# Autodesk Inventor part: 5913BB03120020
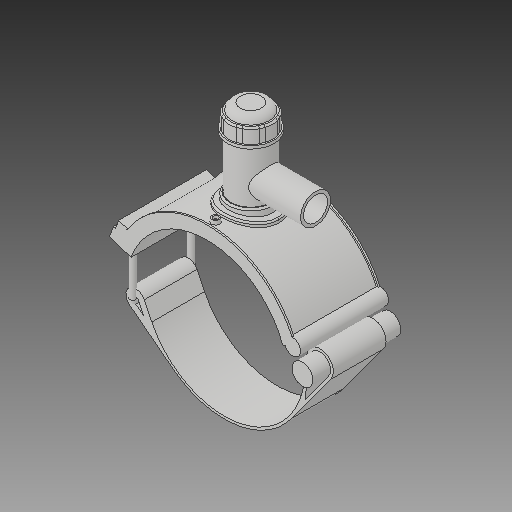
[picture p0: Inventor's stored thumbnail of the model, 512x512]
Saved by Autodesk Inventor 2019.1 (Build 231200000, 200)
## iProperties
Created: 2017-07
Part Number: 5913BB03120020
Material: Generic
Description: PLASSON HIGH VOLUME TAPPING TEE 12''IPS x 2''IPS
Document SubType Name: Modeling
Designer: KIM
Mass: 1712.7 g
Surface Area: 2671.49 cm^2
Volume: 1712.7 cm^3
Density: 1 g/cm^3
Appearance: Default
Author: KIM
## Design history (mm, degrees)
derived "5913B.ipt"
feature "Solid1::5913B.ipt"
feature "Solid2::5913B.ipt"
feature "Solid4::5913B.ipt"
feature "Solid5::5913B.ipt"
tag "TaggingFeature1"
body "Solid1"
body "Solid2"
other parameters: "d0" = 323.4, "d2" = 487.045, "d3" = 80.85, "d4" = 176.022, "d5" = 0, "d6" = 0.1, "d8" = 0, "d40" = 191.71152, "d41" = 113.19, "d43" = 0, "d45" = 0, "d47" = 289.9512, "d78" = 191.7, "d79" = 15, "d80" = 70.4088, "d82" = 5 deg, "d84" = 4, "d85" = 14, "d86" = 0, "d87" = 3, "d88" = 0, "d96" = 376.04952, "d97" = 3.52044, "d98" = 0, "d102" = 3.234, "d120" = 140 deg, "d121" = 24.228, "d122" = 20 deg, "d123" = 921.69, "d124" = 221.2056, "d126" = 0, "d153" = 176.022, "d154" = 0, "d159" = 9.0552, "d162" = 105.6132, "d163" = 0, "d164" = 161.7, "d169" = 4.0905, "d170" = 13.5828, "d172" = 0, "d173" = 1, "d175" = 161.7, "d176" = 20 deg, "d177" = 22.638, "d178" = 45.276, "d180" = 0, "d183" = 18.1104, "d184" = 18.1104, "d187" = 184.338, "d188" = 13.5828, "d189" = 22.638, "d190" = 0, "d191" = 276.507, "d193" = 11.6424, "d194" = 5.8212, "d195" = 90 deg, "d197" = 0, "d199" = 0, "d200" = 22.638, "d202" = 0, "d203" = 194.818, "d204" = 88.17501, "d205" = 64.97106, "d206" = 78.89343, "d207" = 146.1135, "d208" = 151.95804, "d209" = 181.18074, "d210" = 79.82159, "d211" = 92.8158, "d212" = 74.25264, "d213" = 40.392, "d216" = 0, "d217" = 32.34, "d218" = 16.17, "d219" = 3.234, "d222" = 323.4, "d224" = 0, "d230" = 3.234, "d257" = 236.63, "d258" = 129.794, "d259" = 48.08, "d260" = 60.1, "d263" = 194.818, "d265" = 0, "d267" = 13.00006, "d268" = 2.60001, "d269" = 2.60001, "d271" = 2.60001, "d273" = 0, "d274" = 23.56194, "d275" = 258.72, "d277" = 129.36, "d278" = 517.44, "d280" = 0, "d281" = 323.4, "d283" = 0, "d285" = 0, "d290" = 32.34, "d291" = 42.042, "d293" = 177.87, "d294" = 166.551, "d296" = 48.51, "d297" = 38.808, "d_" = 323.4, "B_" = 194.818, "L_" = 176.022, "d_t" = 6, "H_2" = 194.818, "H_1" = 74.93, "d_1" = 60.1, "H_" = 129.794, "d1" = 368.676, "d192" = 11.6424
